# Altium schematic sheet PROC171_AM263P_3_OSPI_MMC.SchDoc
size 431 x 279 mm; Date: Not shown in title block; ApprovedBy: Not shown in title block; CheckedBy: Not shown in title block; Author: Not shown in title block; CompanyName: Not shown in title block; Engineer: Not shown in title block; Organization: Not shown in title block; Address1: Not shown in title block; Address2: Not shown in title block; Address3: Not shown in title block; Address4: Not shown in title block; DocumentNumber: 8; Revision: Use project parameter SCH_Rev; SheetNumber: 8; SheetTotal: 27; PageSetup: Record=PageOptions¦CenterHorizontal=True¦CenterVertical=True¦PrintScale=1.00¦XCorrection=1.00¦YCorrection=1.00¦PrintKind=0¦BorderSize=5000000¦LeftOffset=0¦BottomOffset=0¦Orientation=2¦PaperLength=1000¦PaperWidth=1000¦Scale=100¦PaperSource=15¦PrintQuality=600¦MediaType=1¦DitherType=10¦PaperKind=Letter¦PrintScaleMode=1
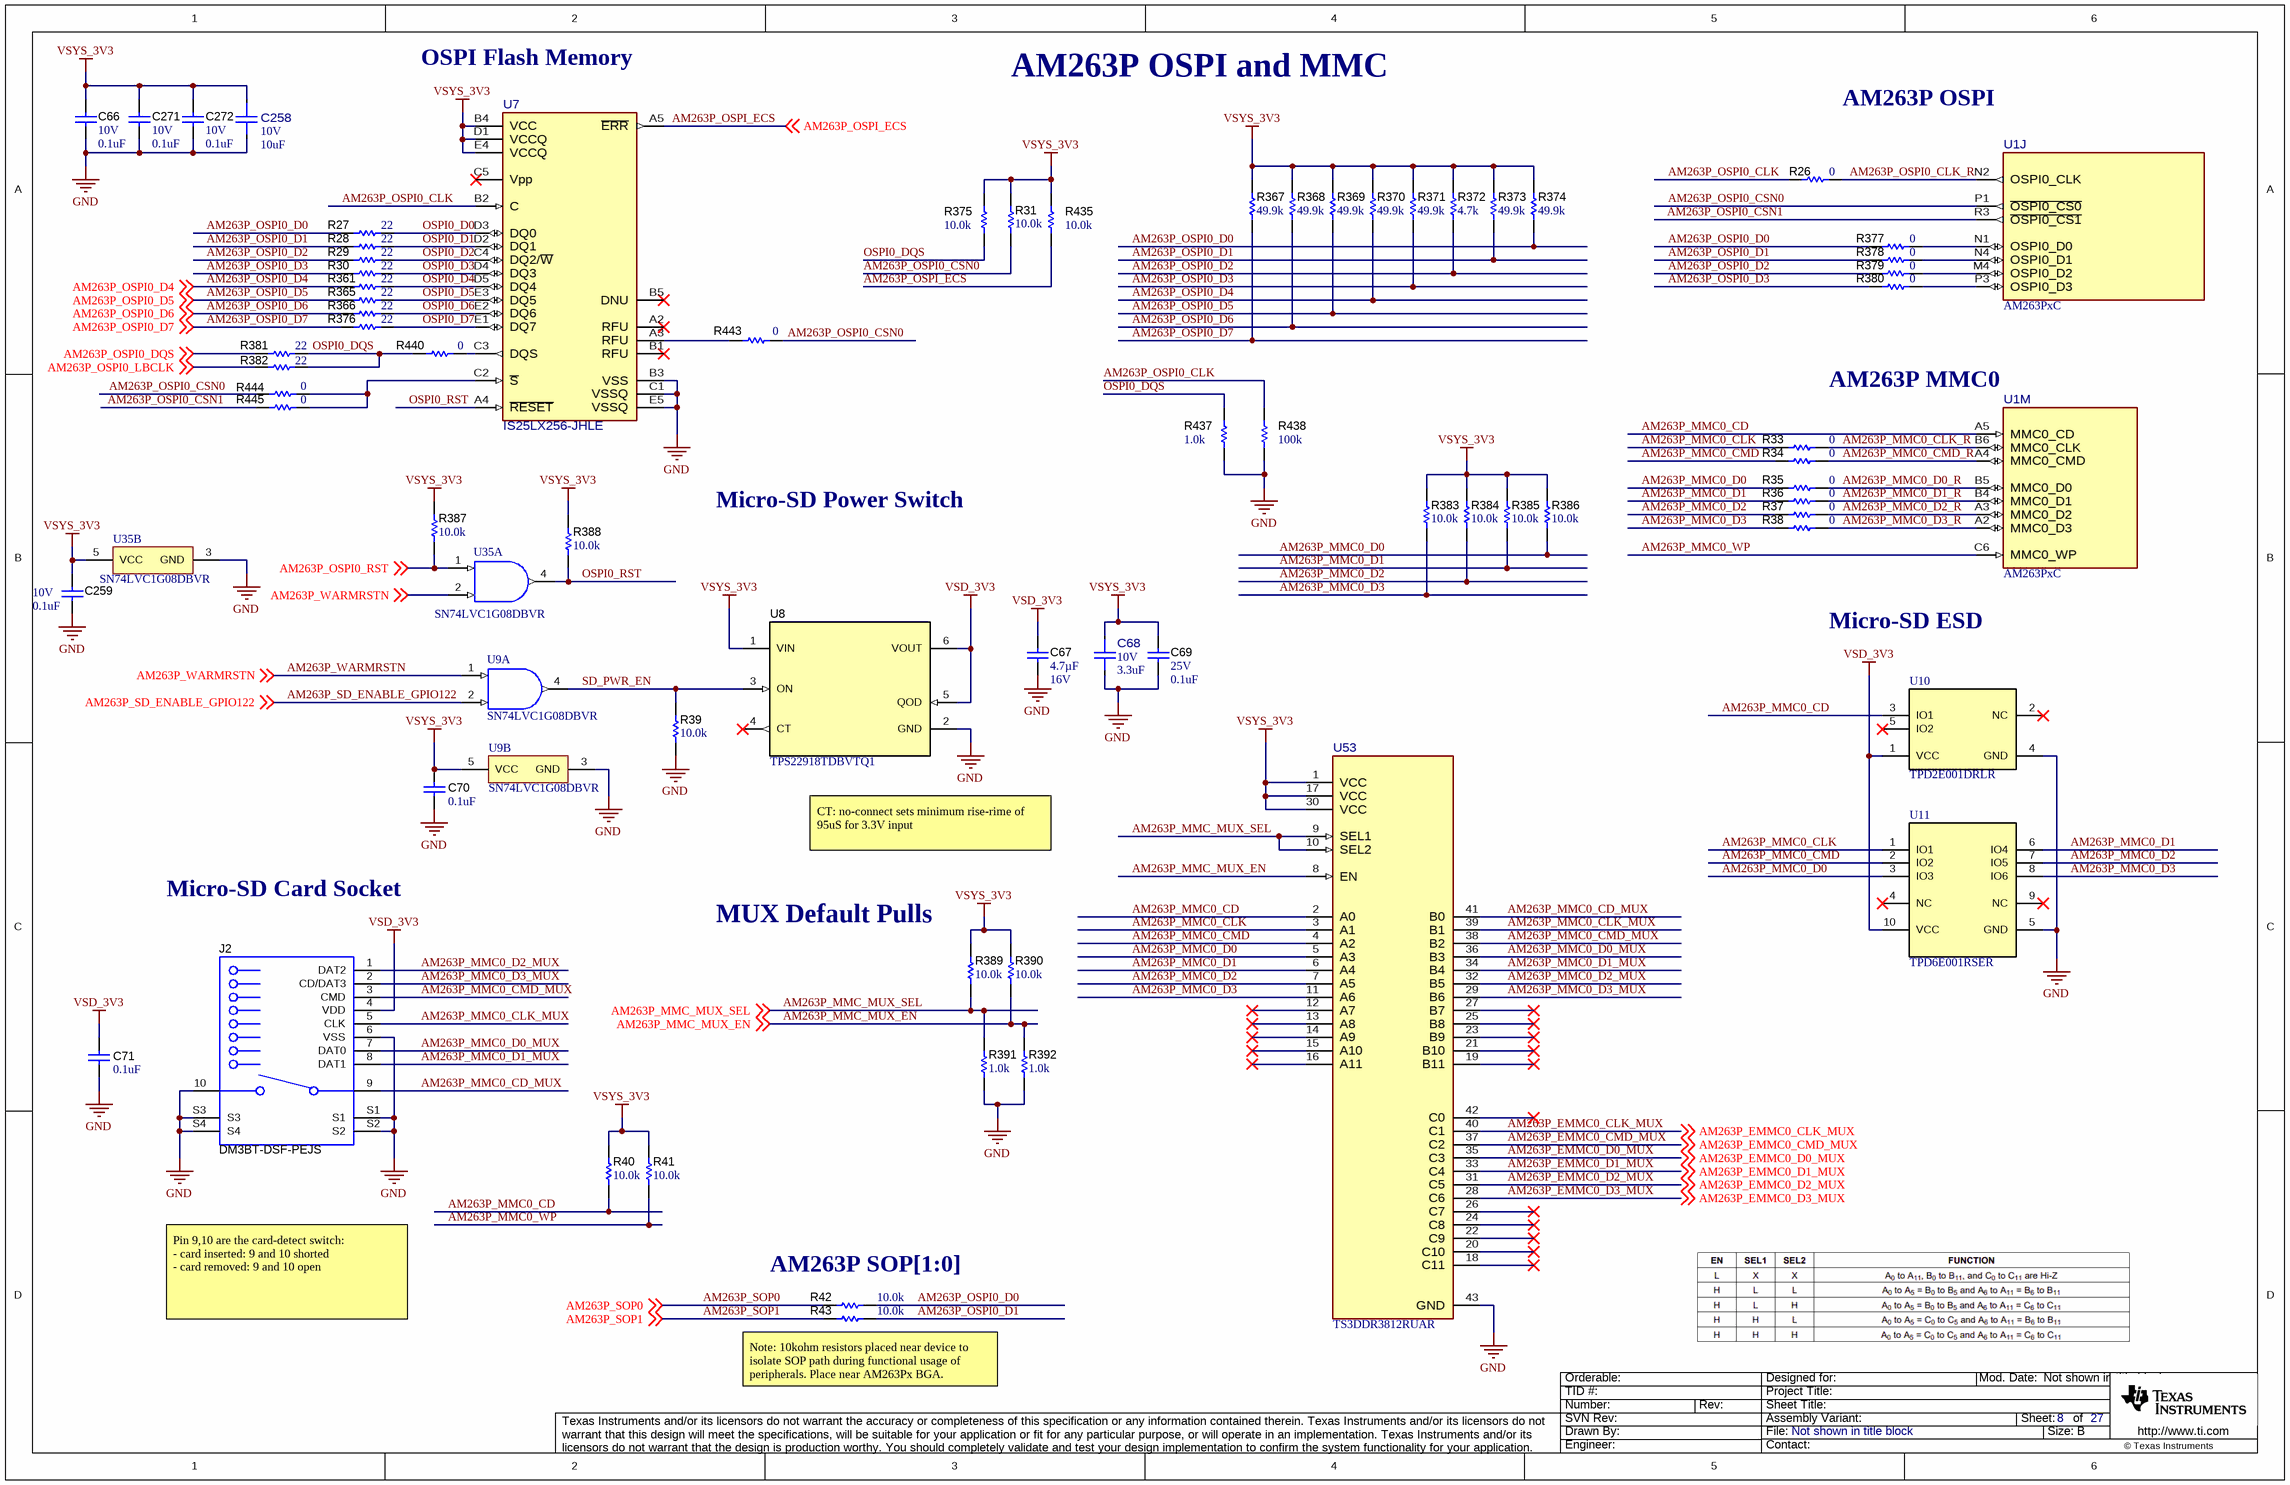
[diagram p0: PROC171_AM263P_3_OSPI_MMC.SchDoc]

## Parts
C66  VDC_V: 10V  ValueDisplayed: 0.1uF  [0402]  (hidden comment: 885012105010)
C67  Cap_F: 4.7µF  VDC_V: 16V  [0603]  (hidden comment: GRM188Z71C475KE21D)
C68  VDC_V: 10V  ValueDisplayed: 3.3uF  [FP-CL10A335KP8NNNC_0603-MFG]  (hidden comment: CL10A335KP8NNNC)
C69  VDC_V: 25V  ValueDisplayed: 0.1uF  [0402]  (hidden comment: GRM155R71E104KE14D)
C70  ValueDisplayed: 0.1uF  [0402]  (hidden comment: GRM155R71E104KE14D)
C71  ValueDisplayed: 0.1uF  [0402]  (hidden comment: GRM155R71E104KE14D)
C258  ValueDisplayed: 10uF  VDC_V: 10V  [FP-KGM05CR51A106MH_0402-MFG]  (hidden comment: KGM05CR51A106MH)
C259  VDC_V: 10V  ValueDisplayed: 0.1uF  [0402]  (hidden comment: 885012105010)
C271  VDC_V: 10V  ValueDisplayed: 0.1uF  [0402]  (hidden comment: 885012105010)
C272  VDC_V: 10V  ValueDisplayed: 0.1uF  [0402]  (hidden comment: 885012105010)
J2  DM3BT-DSF-PEJS  [Hirose_DM3BT-DSF-PEJS]
R26  value 0  [0402L]  (hidden comment: ERJ-2GE0R00X)
R27  Res_ohm: 22  [FP-CRCW020122R0FNED_0201 (0603 metric)-MFG]  (hidden comment: CRCW020122R0FNED)
R28  Res_ohm: 22  [FP-CRCW020122R0FNED_0201 (0603 metric)-MFG]  (hidden comment: CRCW020122R0FNED)
R29  Res_ohm: 22  [FP-CRCW020122R0FNED_0201 (0603 metric)-MFG]  (hidden comment: CRCW020122R0FNED)
R30  Res_ohm: 22  [FP-CRCW020122R0FNED_0201 (0603 metric)-MFG]  (hidden comment: CRCW020122R0FNED)
R31  ValueDisplayed: 10.0k  [0402L]  (hidden comment: CRCW040210K0FKED)
R33  ValueDisplayed: 0  [0402L]  (hidden comment: ERJ-2GE0R00X)
R34  ValueDisplayed: 0  [0402L]  (hidden comment: ERJ-2GE0R00X)
R35  ValueDisplayed: 0  [0402L]  (hidden comment: ERJ-2GE0R00X)
R36  ValueDisplayed: 0  [0402L]  (hidden comment: ERJ-2GE0R00X)
R37  ValueDisplayed: 0  [0402L]  (hidden comment: ERJ-2GE0R00X)
R38  ValueDisplayed: 0  [0402L]  (hidden comment: ERJ-2GE0R00X)
R39  ValueDisplayed: 10.0k  [0402L]  (hidden comment: CRCW040210K0FKED)
R40  ValueDisplayed: 10.0k  [0402L]  (hidden comment: CRCW040210K0FKED)
R41  ValueDisplayed: 10.0k  [0402L]  (hidden comment: CRCW040210K0FKED)
R42  ValueDisplayed: 10.0k  [0402]  (hidden comment: ERJ-2RKF1002X)
R43  ValueDisplayed: 10.0k  [0402]  (hidden comment: ERJ-2RKF1002X)
R361  Res_ohm: 22  [FP-CRCW020122R0FNED_0201 (0603 metric)-MFG]  (hidden comment: CRCW020122R0FNED)
R365  Res_ohm: 22  [FP-CRCW020122R0FNED_0201 (0603 metric)-MFG]  (hidden comment: CRCW020122R0FNED)
R366  Res_ohm: 22  [FP-CRCW020122R0FNED_0201 (0603 metric)-MFG]  (hidden comment: CRCW020122R0FNED)
R367  ValueDisplayed: 49.9k  [0402]  (hidden comment: ERJ-2RKF4992X)
R368  ValueDisplayed: 49.9k  [0402]  (hidden comment: ERJ-2RKF4992X)
R369  ValueDisplayed: 49.9k  [0402]  (hidden comment: ERJ-2RKF4992X)
R370  ValueDisplayed: 49.9k  [0402]  (hidden comment: ERJ-2RKF4992X)
R371  ValueDisplayed: 49.9k  [0402]  (hidden comment: ERJ-2RKF4992X)
R372  ValueDisplayed: 4.7k  [0402]  (hidden comment: CRCW04024K70JNED)
R373  ValueDisplayed: 49.9k  [0402]  (hidden comment: ERJ-2RKF4992X)
R374  ValueDisplayed: 49.9k  [0402]  (hidden comment: ERJ-2RKF4992X)
R375  ValueDisplayed: 10.0k  [0402L]  (hidden comment: CRCW040210K0FKED)
R376  Res_ohm: 22  [FP-CRCW020122R0FNED_0201 (0603 metric)-MFG]  (hidden comment: CRCW020122R0FNED)
R377  value 0  [0402L]  (hidden comment: ERJ-2GE0R00X)
R378  value 0  [0402L]  (hidden comment: ERJ-2GE0R00X)
R379  value 0  [0402L]  (hidden comment: ERJ-2GE0R00X)
R380  value 0  [0402L]  (hidden comment: ERJ-2GE0R00X)
R381  Res_ohm: 22  [FP-CRCW020122R0FNED_0201 (0603 metric)-MFG]  (hidden comment: CRCW020122R0FNED)
R382  ValueDisplayed: 22  [0402]  (hidden comment: CRCW040222R0JNED)
R383  ValueDisplayed: 10.0k  [0402L]  (hidden comment: CRCW040210K0FKED)
R384  ValueDisplayed: 10.0k  [0402L]  (hidden comment: CRCW040210K0FKED)
R385  ValueDisplayed: 10.0k  [0402L]  (hidden comment: CRCW040210K0FKED)
R386  ValueDisplayed: 10.0k  [0402L]  (hidden comment: CRCW040210K0FKED)
R387  ValueDisplayed: 10.0k  [0402L]  (hidden comment: CRCW040210K0FKED)
R388  ValueDisplayed: 10.0k  [0402L]  (hidden comment: CRCW040210K0FKED)
R389  ValueDisplayed: 10.0k  [0402]  (hidden comment: ERJ-2RKF1002X)
R390  ValueDisplayed: 10.0k  [0402]  (hidden comment: ERJ-2RKF1002X)
R391  ValueDisplayed: 1.0k  [0402]  (hidden comment: ERJ-2GEJ102X)
R392  ValueDisplayed: 1.0k  [0402]  (hidden comment: ERJ-2GEJ102X)
R435  ValueDisplayed: 10.0k  [0402L]  (hidden comment: CRCW040210K0FKED)
R437  ValueDisplayed: 1.0k  [0402]  (hidden comment: ERJ-2GEJ102X)
R438  ValueDisplayed: 100k  [0402]  (hidden comment: ERJ-2RKF1003X)
R440  ValueDisplayed: 0  [0402L]  (hidden comment: ERJ-2GE0R00X)
R443  value 0  [0402L]  (hidden comment: ERJ-2GE0R00X)
R444  ValueDisplayed: 0  [0402L]  (hidden comment: ERJ-2GE0R00X)
R445  ValueDisplayed: 0  [0402L]  (hidden comment: ERJ-2GE0R00X)
U1  AM263PxC  [ZCZ0324A-MFG]  (parts J,M of 13)
U7  IS25LX256-JHLE  [FP-IS25LX256-JHLE_TFBGA24-IPC_C]
U8  TPS22918TDBVTQ1  [DBV0006A_N]
U9  SN74LVC1G08DBVR  [DBV0005A_N]  (parts A,B of 2)
U10  TPD2E001DRLR  [DRL0005A]
U11  TPD6E001RSER  [RSE0010A]
U35  SN74LVC1G08DBVR  [DBV0005A_N]  (parts A,B of 2)
U53  TS3DDR3812RUAR  [RUA0042A-MFG]

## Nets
GND: C66.2 C67.2 C68.2 C69.2 C70.1 C71.1 C258.2 C259.2 C271.2 C272.2 J2.6(VSS) J2.10(B) J2.S1 J2.S2 J2.S3 J2.S4 R39.1 R391.1 R392.1 R437.1 R438.1 U7.B3(VSS) U7.C1(VSSQ) U7.E5(VSSQ) U8.2(GND) U9.3(GND) U10.4(GND) U11.5(GND) U35.3(GND) U53.43(GND)
VSD_3V3: C67.1 C71.2 J2.4(VDD) U8.5(QOD) U8.6(VOUT) U10.1(VCC) U11.10(VCC)
VSYS_3V3: C66.1 C68.1 C69.1 C70.2 C258.1 C259.1 C271.1 C272.1 R31.1 R40.2 R41.2 R367.1 R368.1 R369.1 R370.1 R371.1 R372.2 R373.1 R374.1 R375.2 R383.2 R384.2 R385.2 R386.2 R387.2 R388.2 R389.1 R390.1 R435.2 U7.B4(VCC) U7.D1(VCCQ) U7.E4(VCCQ) U8.1(VIN) U9.5(VCC) U35.5(VCC) U53.1(VCC) U53.17(VCC) U53.30(VCC)
AM263P_EMMC0_CLK_MUX: U53.40(C1) ; off-sheet AM263P_EMMC0_CLK_MUX
AM263P_EMMC0_CMD_MUX: U53.37(C2) ; off-sheet AM263P_EMMC0_CMD_MUX
AM263P_EMMC0_D0_MUX: U53.35(C3) ; off-sheet AM263P_EMMC0_D0_MUX
AM263P_EMMC0_D1_MUX: U53.33(C4) ; off-sheet AM263P_EMMC0_D1_MUX
AM263P_EMMC0_D2_MUX: U53.31(C5) ; off-sheet AM263P_EMMC0_D2_MUX
AM263P_EMMC0_D3_MUX: U53.28(C6) ; off-sheet AM263P_EMMC0_D3_MUX
AM263P_MMC0_CD: R40.1 U1.A5(MMC0_CD) U10.3(IO1) U53.2(A0)
AM263P_MMC0_CD_MUX: J2.9(A) U53.41(B0)
AM263P_MMC0_CLK: R33.2 U11.1(IO1) U53.3(A1)
AM263P_MMC0_CLK_MUX: J2.5(CLK) U53.39(B1)
AM263P_MMC0_CLK_R: R33.1 U1.B6(MMC0_CLK)
AM263P_MMC0_CMD: R34.2 U11.2(IO2) U53.4(A2)
AM263P_MMC0_CMD_MUX: J2.3(CMD) U53.38(B2)
AM263P_MMC0_CMD_R: R34.1 U1.A4(MMC0_CMD)
AM263P_MMC0_D0: R35.2 R386.1 U11.3(IO3) U53.5(A3)
AM263P_MMC0_D0_MUX: J2.7(DAT0) U53.36(B3)
AM263P_MMC0_D0_R: R35.1 U1.B5(MMC0_D0)
AM263P_MMC0_D1: R36.2 R385.1 U11.6(IO4) U53.6(A4)
AM263P_MMC0_D1_MUX: J2.8(DAT1) U53.34(B4)
AM263P_MMC0_D1_R: R36.1 U1.B4(MMC0_D1)
AM263P_MMC0_D2: R37.2 R384.1 U11.7(IO5) U53.7(A5)
AM263P_MMC0_D2_MUX: J2.1(DAT2) U53.32(B5)
AM263P_MMC0_D2_R: R37.1 U1.A3(MMC0_D2)
AM263P_MMC0_D3: R38.2 R383.1 U11.8(IO6) U53.11(A6)
AM263P_MMC0_D3_MUX: J2.2(CD/DAT3) U53.29(B6)
AM263P_MMC0_D3_R: R38.1 U1.A2(MMC0_D3)
AM263P_MMC0_WP: R41.1 U1.C6(MMC0_WP)
AM263P_MMC_MUX_EN: R390.2 R392.2 U53.8(EN) ; off-sheet AM263P_MMC_MUX_EN
AM263P_MMC_MUX_SEL: R389.2 R391.2 U53.9(SEL1) U53.10(SEL2) ; off-sheet AM263P_MMC_MUX_SEL
AM263P_OSPI0_CLK: R26.1 R438.2 U7.B2(C)
AM263P_OSPI0_CLK_R: R26.2 U1.N2(OSPI0_CLK)
AM263P_OSPI0_CSN0: R31.2 R443.2 R444.2 U1.P1(~{OSPI0_CS0})
AM263P_OSPI0_CSN1: R445.2 U1.R3(~{OSPI0_CS1})
AM263P_OSPI0_D0: R27.1 R42.1 R374.2 R377.1
AM263P_OSPI0_D1: R28.1 R43.1 R373.2 R378.1
AM263P_OSPI0_D2: R29.1 R372.1 R379.1
AM263P_OSPI0_D3: R30.1 R371.2 R380.1
AM263P_OSPI0_D4: R361.1 R370.2 ; off-sheet AM263P_OSPI0_D4
AM263P_OSPI0_D5: R365.1 R369.2 ; off-sheet AM263P_OSPI0_D5
AM263P_OSPI0_D6: R366.1 R368.2 ; off-sheet AM263P_OSPI0_D6
AM263P_OSPI0_D7: R367.2 R376.1 ; off-sheet AM263P_OSPI0_D7
AM263P_OSPI0_DQS: R381.1 ; off-sheet AM263P_OSPI0_DQS
AM263P_OSPI0_LBCLK: R382.1 ; off-sheet AM263P_OSPI0_LBCLK
AM263P_OSPI0_RST: R387.1 U35.1(A) ; off-sheet AM263P_OSPI0_RST
AM263P_OSPI_ECS: R435.1 U7.A5(~{ERR}) ; off-sheet AM263P_OSPI_ECS
AM263P_SD_ENABLE_GPIO122: U9.2(B) ; off-sheet AM263P_SD_ENABLE_GPIO122
AM263P_SOP0: R42.2 ; off-sheet AM263P_SOP0
AM263P_SOP1: R43.2 ; off-sheet AM263P_SOP1
AM263P_WARMRSTN: U9.1(A) U35.2(B) ; off-sheet AM263P_WARMRSTN
OSPI0_D0: R27.2 U7.D3(DQ0)
OSPI0_D1: R28.2 U7.D2(DQ1)
OSPI0_D2: R29.2 U7.C4(DQ2/~{W})
OSPI0_D3: R30.2 U7.D4(DQ3)
OSPI0_D4: R361.2 U7.D5(DQ4)
OSPI0_D5: R365.2 U7.E3(DQ5)
OSPI0_D6: R366.2 U7.E2(DQ6)
OSPI0_D7: R376.2 U7.E1(DQ7)
OSPI0_DQS: R375.1 R381.2 R382.2 R437.2 R440.2
OSPI0_RST: R388.1 U7.A4(~{RESET}) U35.4(Y)
SD_PWR_EN: R39.2 U8.3(ON) U9.4(Y)
NetR377_2: R377.2 U1.N1(OSPI0_D0)
NetR378_2: R378.2 U1.N4(OSPI0_D1)
NetR379_2: R379.2 U1.M4(OSPI0_D2)
NetR380_2: R380.2 U1.P3(OSPI0_D3)
NetR440_1: R440.1 U7.C3(DQS)
NetR443_1: R443.1 U7.A3(RFU)
NetR444_1: R444.1 R445.1 U7.C2(~{S})

Not connected (* = marked no-connect by the designer): U7 A2(RFU)* B1(RFU)* B5(DNU)* C5(Vpp)*; U8 4(CT)*; U10 2(NC)* 5(IO2)*; U11 4(NC)* 9(NC)*; U53 12(A7)* 13(A8)* 14(A9)* 15(A10)* 16(A11)* 18(C11)* 19(B11)* 20(C10)* 21(B10)* 22(C9)* 23(B9)* 24(C8)* 25(B8)* 26(C7)* 27(B7)* 42(C0)*

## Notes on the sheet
- OSPI Flash Memory
- AM263P OSPI and MMC
- AM263P OSPI
- AM263P MMC0
- Micro-SD Power Switch
- Micro-SD ESD
- Micro-SD Card Socket
- CT: no-connect sets minimum rise-rime of 95uS for 3.3V input
- (near R389) MUX Default Pulls
- AM263P SOP[1:0]
- Pin 9,10 are the card-detect switch:
  - card inserted: 9 and 10 shorted
  - card removed: 9 and 10 open
- (near R43) Note: 10kohm resistors placed near device to isolate SOP path during functional usage of peripherals. Place near AM263Px BGA.

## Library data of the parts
C66 C259 C271 C272 = CMP-0006221-2: CAP, CERM, 0.1 uF, 10 V, +/- 20%, X5R, 0402; Manufacturer: Wurth Elektronik; TaMin_C: -55°C; Polarized: N; SizeAreaWB_mm2: 3; Value1: Unknown; U/M: EA; Value: 0.1uF; TaMax_C: 85°C; SizeZ_mm: 0.6; SizeX_mm: 1; SizeY_mm: 0.5; Cap_F: 100nF; AEC Category: Q200
C67 = CMP-0064936-4: CAP, CERM, 4.7 uF, 16 V,+/- 10%, X7R, 0603; Manufacturer: MuRata; TaMin_C: -55°C; Polarized: N; SizeAreaWB_mm2: 4.68; Value1: Unknown; U/M: EA; Value: 4.7uF; TaMax_C: 125°C; SizeZ_mm: 1; SizeX_mm: 1.6; SizeY_mm: 0.8; SizeArea_mm2: 1.28; AEC Category: Q200
C68 = CMP-0042976-1: Cap Ceramic 3.3uF 10V X5R ±10% Pad SMD 0603 +85°C T/R; Manufacturer: Samsung; TempCo: 15%; Value: 3.3µF; SizeZ_mm: 0.9mm; AEC Qualified: No
C69 = CMP-0006659-2: CAP, CERM, 0.1 uF, 25 V, +/- 10%, X7R, 0402; Manufacturer: MuRata; TaMin_C: -55°C; Polarized: N; SizeAreaWB_mm2: 3; Value1: Unknown; U/M: EA; Value: 0.1uF; TaMax_C: 125°C; SizeZ_mm: 0.6; SizeX_mm: 1; SizeY_mm: 0.5; Cap_F: 100nF; AEC Category: Q200
C70 C71 = CMP-0006659-2: CAP, CERM, 0.1 uF, 25 V, +/- 10%, X7R, 0402; Manufacturer: MuRata; TaMin_C: -55°C; Polarized: N; SizeAreaWB_mm2: 3; U/M: EA; Value: 0.1uF; TaMax_C: 125°C; SizeZ_mm: 0.6; SizeX_mm: 1; SizeY_mm: 0.5; Value2: 25V; Cap_F: 100nF; AEC Category: Q200; Value1: Unknown
C258 = CMP-0043010-1: 10 µF ±20% 10V Ceramic Capacitor X5R 0402 (1005 Metric); Manufacturer: KYOCERA AVX; AEC Qualified: No; Cap_F: 10µF; SizeZ_mm: 0.7mm; TempCo: 15%; Value: 10µF
J2 = CMP-0080007-1: Conncetor, micro SD, 8+2 Pos, R/A, SMT; Manufacturer: Hirose Electric Co. Ltd.; Pitch_mm: 1.1; Gender: Female; ContactFinish: Gold; Row_Count: 1; CompType: Connector
R26 R377-R380 R443 = CMP-0026992-3: RES, 0, 5%, 0.1 W, AEC-Q200 Grade 0, 0402; Manufacturer: Panasonic; Power_W: 100mW; TempCo: 600 ppm/C; Value_Code: 0000; EIA_Code: E24; SizeX_mm: 1; SizeY_mm: 0.5; SizeZ_mm: 0.6; Value2: 0.1W; AEC Qualified: Y; VDC_V: 50V; AEC Category: Q200; SizeAreaWB_mm2: 3
R27-R30 R361 R365 R366 R376 R381 = CMP-0087090-2: RES Thick Film SMD 22Ω 1% 1/20W 0201 200ppm/°C; Manufacturer: Vishay; SizeZ_mm: 0.28mm; VDC_V: 30V; Power_W: 50mW; AEC Qualified: No
R31 R39-R41 R375 R383-R388 R435 = CMP-0025958-3: RES, 10.0 k, 1%, 0.063 W, AEC-Q200 Grade 0, 0402; Manufacturer: Vishay-Dale; Power_W: 63mW; TempCo: 100 ppm/C; Value_Code: 10k0; Value: 10.0k; EIA_Code: E96; Res_ohm: 10k; SizeX_mm: 1; SizeY_mm: 0.5; SizeZ_mm: 0.6; Value2: 0.063W; AEC Qualified: Y; VDC_V: 50V; AEC Category: Q200; AEC Grade: 0
R33-R38 R440 R444 R445 = CMP-0026992-3: RES, 0, 5%, 0.1 W, AEC-Q200 Grade 0, 0402; Manufacturer: Panasonic; Power_W: 100mW; TempCo: 600 ppm/C; Value_Code: 0000; Value: 0; EIA_Code: E24; SizeX_mm: 1; SizeY_mm: 0.5; SizeZ_mm: 0.6; Value2: 0.1W; AEC Qualified: Y; VDC_V: 50V; AEC Category: Q200; SizeAreaWB_mm2: 3
R42 R43 R389 R390 = CMP-0026658-1: RES, 10.0 k, 1%, 0.1 W, 0402; Manufacturer: Panasonic; Power_W: 100mW; TempCo: 100 ppm/C; Value_Code: 10k0; U/M: EA; Value: 10.0k; EIA_Code: E96; Res_ohm: 10k; SizeX_mm: 1; SizeY_mm: 0.5; SizeZ_mm: 0.6; Value2: 0.1W; VDC_V: 50V; AEC Category: Q200
R367-R371 R373 R374 = CMP-0026702-1: RES, 49.9 k, 1%, 0.1 W, AEC-Q200 Grade 0, 0402; Manufacturer: Panasonic; Power_W: 100mW; TempCo: 100 ppm/C; Value_Code: 49k9; U/M: EA; Value: 49.9k; EIA_Code: E96; SizeX_mm: 1; SizeY_mm: 0.5; SizeZ_mm: 0.6; Value2: 0.1W; AEC Qualified: Y; VDC_V: 50V; AEC Grade: 0; AEC Category: Q200
R372 = CMP-0026938-5: RES, 4.7 k, 5%, 0.063 W, AEC-Q200 Grade 0, 0402; Manufacturer: Vishay-Dale; Power_W: 63mW; TempCo: 200 ppm/C; Value_Code: 4k70; Value: 4.7k; EIA_Code: E24; SizeX_mm: 1; SizeY_mm: 0.5; SizeZ_mm: 0.6; Value2: 0.063W; AEC Qualified: Y; VDC_V: 50V; AEC Category: Q200; AEC Grade: 0
R382 = CMP-0026880-3: RES, 22, 5%, 0.063 W, AEC-Q200 Grade 0, 0402; Manufacturer: Vishay-Dale; Power_W: 63mW; TempCo: 200 ppm/C; Value_Code: 22R0; Value: 22; EIA_Code: E24; SizeX_mm: 1; SizeY_mm: 0.5; SizeZ_mm: 0.6; Value2: 0.063W; AEC Qualified: Y; VDC_V: 50V; AEC Category: Q200; AEC Grade: 0
R391 R392 R437 = CMP-0078193-1: RES, 1.0 k, 5%, 0.1 W, AEC-Q200 Grade 0, 0402; Manufacturer: Panasonic; Value_Code: 1k00; SizeArea_mm2: 0.5; AEC Qualified: Y; AEC Category: Q200; Res_ohm: 1k; Value: 1.0k; SizeZ_mm: 0.6; Green_REACh: Passed; EIA_Code: E24; TempCo: 200 ppm/C; AEC Grade: 0; Power_W: 100mW; VDC_V: 50V; Value2: 0.1W; Green_Lifecycle: Active; U/M: EA; SizeX_mm: 1
R438 = CMP-0026659-2: RES, 100 k, 1%, 0.1 W, 0402; Manufacturer: Panasonic; U/M: EA; Value2: 0.1W; EIA_Code: E96; Value: 100k; SizeArea_mm2: 0.5; TempCo: 100 ppm/C; SizeZ_mm: 0.6; AEC Category: Q200; VDC_V: 50V; Power_W: 100mW; AEC Grade: 0; SizeX_mm: 1; AEC Qualified: Yes
U1 = CMP-0001698-2: Sitara™ Microcontroller; Manufacturer: Texas Instruments; SizeZ_mm: 1.4mm; Core Architecture: ARM Cortex-R5F; Data Bus Width: 32bits; Frequency_Fixed: 200MHz; Interface: I2C,SPI,UART,CAN,LIN,Ethernet,Other; Max Supply Voltage: 3.465V; Memory Size: 2MBytes; Memory Type: RAM; Min Supply Voltage: 1.14V; Number Of Cores: 1; Number Of I/Os: 140; Number Of I2C Channels: 4; Number Of Spi Channels: 5; Number Of Uart Channels: 6; Standoff Height: 0.35mm; AEC Category: Q200; CompType: IC
U7 = CMP-0125522-1: FLASH Memory IC 256Mbit SPI - Octal I/O 133 MHz 6 ns 24-TFBGA (6x8); Manufacturer: ISSI; SizeZ_mm: 1.2mm; Access Time: 6ns; Frequency_Fixed: 133MHz; Max Supply Voltage: 3.6V; Min Supply Voltage: 2.7V; Nominal Supply Current: 0.13-48mA; Standoff Height: 0.26mm; TaMax_C: +105°C; TaMin_C: -40°C
U8 = CMP-0081995-1: 5.5V, 2A, 52mΩ Automotive High-Side Load Switch with Adjustable Rise Time & Quick Output Discharge, DBV0006A (SOT-23-6); Alternate PartNumber: TPS22918TDBVRQ1; Alternate Manufacturer: Texas Instruments; SizeAreaWB_mm2: 14.82; SizeZ_mm: 1.45; SizeX_mm: 2.8; SizeY_mm: 2.9; SizeArea_mm2: 8.12; CompType: IC; AEC Qualified: Y; AEC Category: Q200
U9 U35 = CMP-0051588-2: Single 2-Input Positive-AND Gate, DBV0005A, LARGE T&R; Manufacturer: Texas Instruments; Logic: True; ICC @ Nom Voltage(Max)(mA): 0.01; VCC(Min)(V): 1.65; Bits(#): 1; Rating: Catalog; Schmitt Trigger: No; Voltage(Nom)(V): 1.8,2.5,3.3,5; Output Drive (IOL/IOH)(Max)(mA): 32/-32; Gate Type: AND; tpd @ Nom Voltage(Max)(ns): 4.5,6,4,5; VCC(Max)(V): 5.5; Output Type: CMOS; F @ Nom Voltage(Max)(Mhz): 150; Input Type: CMOS/TTL; Technology Family: LVC; AEC Category: Q200; AEC Qualified: N; CompType: IC
U10 = CMP-0043096-2: Low-Capacitance + / - 15 kV ESD-Protection Array for High-Speed Data Interfaces, 2 Channels, -40 to +85 degC, 5-pin SOT (DRL), Green (RoHS & no Sb/Br); Manufacturer: Texas Instruments; IO Leakage Current(nA): 1; IO Capacitance(Typ)(pF): 1.5; USB High Speed: TRUE; SubFamily: ESD Solution; Breakdown Voltage(Min)(V): 11; IEC 61000-4-2 Air-Gap(+/- kV): 15; IEC 61000-4-2 Contact(+/- kV): 8
U11 = CMP-0043123-1: Low-Capacitance + / - 15 kV ESD Protection Array for High-Speed Data Interfaces, 6 Channels, -40 to +85 degC, 10-pin UQFN (RSE), Green (RoHS & no Sb/Br); Manufacturer: Texas Instruments; Serial ATA / eSATA: TRUE; IO Leakage Current(nA): 1; IO Capacitance(Typ)(pF): 1.5; IEC 61000-4-2 Contact(+/- kV): 8; Breakdown Voltage(Min)(V): 11; IEC 61000-4-2 Air-Gap(+/- kV): 15; SubFamily: ESD Solution
U53 = CMP-0093539-2: IC MUX/DEMUX DDR3 1:2 42WQFN; Manufacturer: Texas Instruments; TaMax_C: +85°C; TaMin_C: -40°C; On State Resistance: 8Ω; SizeZ_mm: 0.8mm; Min Supply Voltage: 3V; Standoff Height: 0mm; Max Supply Voltage: 3.6V; AEC Qualified: No; PositionCount: 12; -3Db Bandwith: 1.675GHz; Nominal Supply Current: 300uA; AEC Category: Q200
